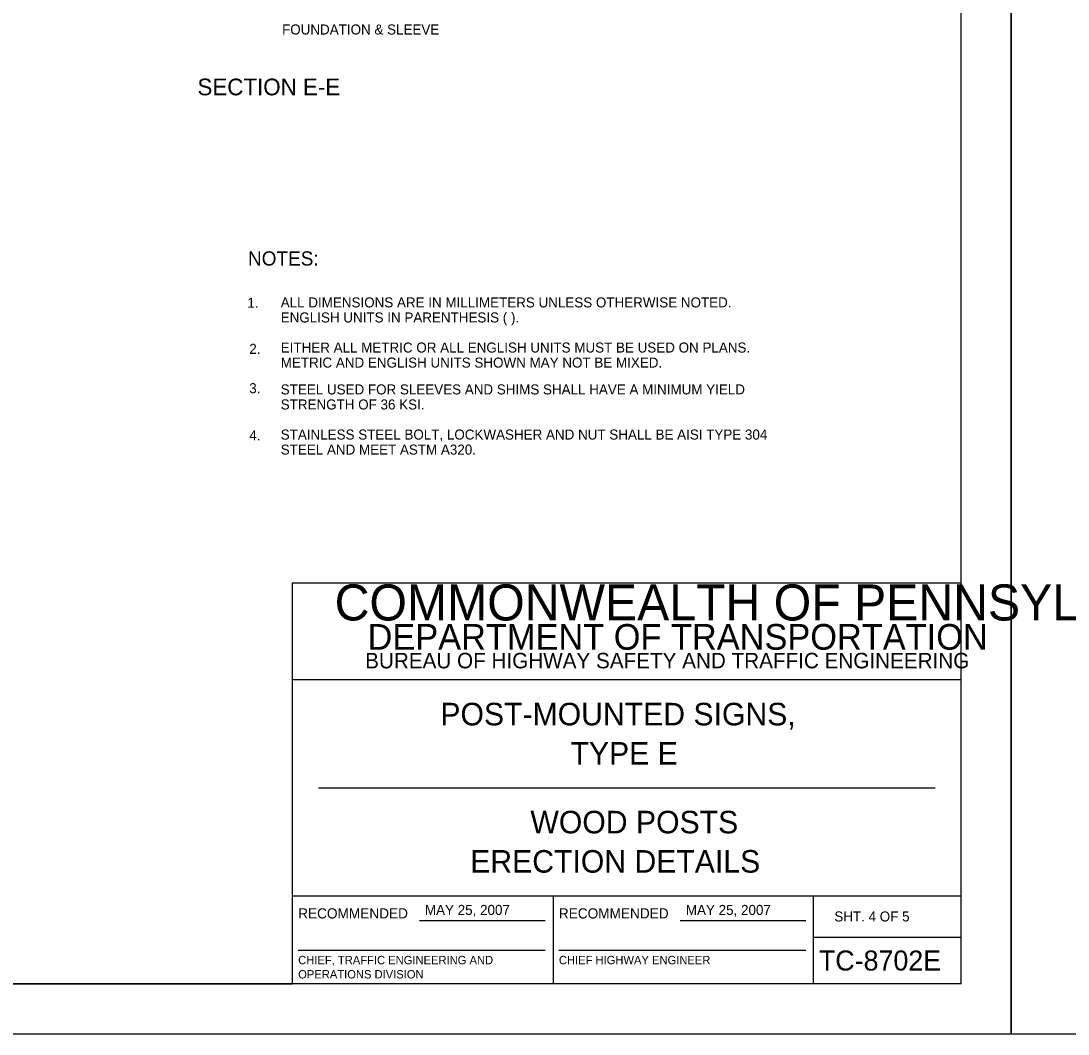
# Model space of a CAD drawing. Extents: x -1958 to 628, y -879 to 309.
# Drawn here: x -1413.6 to -1100.4, y -878.6 to -575.5 of the extents above; entities that cross this region are included whole.
import ezdxf

# ---------------------------------------------------------------- set-up
doc = ezdxf.new("R2010")
doc.units = 0
for name, color, linetype in [('1', 7, 'Continuous'), ('2', 7, 'Continuous'), ('3', 7, 'Continuous'), ('4', 7, 'Continuous'), ('PLT-BNDY', 7, 'Continuous')]:
    doc.layers.add(name, color=color, linetype=linetype)

msp = doc.modelspace()

# ---------------------------------------------------------------- linework, layer by layer
at = {"layer": '1'}
for p, q in [((-1132.39, -863.56), (-1132.39, -299.56)), ((-1332.39, -863.56), (-1332.39, -743.56)), ((-1332.39, -743.56), (-1132.39, -743.56)), ((-1132.39, -772.56), (-1332.39, -772.56)), ((-1324.64, -804.88), (-1140.14, -804.88)), ((-1332.39, -837.19), (-1132.39, -837.19)), ((-1254.39, -837.19), (-1254.39, -863.56)), ((-1176.51, -863.56), (-1176.51, -837.19)), ((-1294.45, -844.62), (-1256.83, -844.62)), ((-1216.45, -844.62), (-1178.83, -844.62)), ((-1176.51, -849.56), (-1132.39, -849.56)), ((-1330.7, -853.51), (-1256.83, -853.51)), ((-1252.7, -853.51), (-1178.83, -853.51)), ((-1132.39, -863.56), (-1918.39, -863.56)), ((-1918.39, -863.56), (-1332.39, -863.56))]:
    msp.add_line(p, q, dxfattribs=at)
at = {"layer": 'PLT-BNDY'}
for points in [[(-1958.39, -284.56), (-1117.39, -284.56), (-1117.39, -878.56), (-1958.39, -878.56)], [(-1117.39, -284.56), (-276.39, -284.56), (-276.39, -878.56), (-1117.39, -878.56)]]:
    msp.add_lwpolyline(points, close=True, dxfattribs=at)

# ---------------------------------------------------------------- texts
at = {"layer": '1'}
for s, height, p in [('COMMONWEALTH OF PENNSYLVANIA', 10.7827, (-1319.79, -754.83)), ('DEPARTMENT OF TRANSPORTATION', 7.6838, (-1309.93, -763.58)), ('BUREAU OF HIGHWAY SAFETY AND TRAFFIC ENGINEERING', 4.6252, (-1310.66, -769.15)), ('POST-MOUNTED SIGNS,', 6.75, (-1288.16, -786.22)), ('TYPE E', 6.75, (-1249.23, -797.97)), ('WOOD POSTS', 6.75, (-1261.23, -818.53)), ('ERECTION DETAILS', 6.75, (-1279.23, -830.28)), ('RECOMMENDED', 3.048, (-1330.7, -843.99)), ('RECOMMENDED', 3.048, (-1252.7, -843.99)), ('SHT. 4 OF 5', 3, (-1170.3, -844.88)), ('CHIEF, TRAFFIC ENGINEERING AND', 2.5, (-1330.7, -857.68)), ('CHIEF HIGHWAY ENGINEER', 2.5, (-1252.7, -857.68)), ('TC-8702E', 6, (-1174.91, -859.56)), ('OPERATIONS DIVISION', 2.5, (-1330.7, -861.93))]:
    msp.add_text(s, height=height, dxfattribs=at).set_placement(p)
at = {"layer": '2'}
for s, height, p in [('  FOUNDATION & SLEEVE', 3, (-1337.75, -579.53)), ('SECTION E-E', 5, (-1360.84, -597.72)), ('MAY 25, 2007', 3, (-1292.78, -842.93)), ('MAY 25, 2007', 3, (-1214.71, -842.93))]:
    msp.add_text(s, height=height, dxfattribs=at).set_placement(p)
at = {"layer": '3'}
msp.add_text('NOTES:', height=4.25, dxfattribs=at).set_placement((-1345.72, -648.65))
at = {"layer": '4'}
for s, p in [('1.', (-1345.92, -661.29)), ('ALL DIMENSIONS ARE IN MILLIMETERS UNLESS OTHERWISE NOTED. ', (-1335.92, -661.18)), ('ENGLISH UNITS IN PARENTHESIS ( ).', (-1335.92, -665.68)), ('2.', (-1345.34, -675.07)), ('EITHER ALL METRIC OR ALL ENGLISH UNITS MUST BE USED ON PLANS.  ', (-1335.92, -674.68)), ('METRIC AND ENGLISH UNITS SHOWN MAY NOT BE MIXED.', (-1335.92, -679.18)), ('3.', (-1345.34, -686.84)), ('STEEL USED FOR SLEEVES AND SHIMS SHALL HAVE A MINIMUM YIELD', (-1335.92, -687.21)), ('STRENGTH OF 36 KSI.', (-1335.92, -691.71)), ('4.', (-1345.34, -700.97)), ('STAINLESS STEEL BOLT, LOCKWASHER AND NUT SHALL BE AISI TYPE 304', (-1335.92, -700.71)), ('STEEL AND MEET ASTM A320.', (-1335.92, -705.21))]:
    msp.add_text(s, height=3, dxfattribs=at).set_placement(p)

doc.saveas('drawing.dxf')
